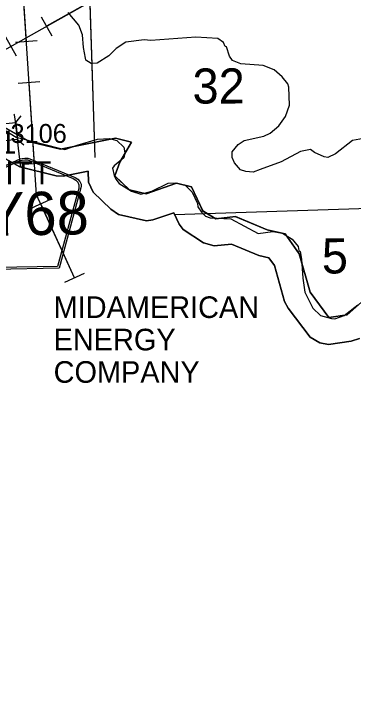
# Model space of a CAD drawing. Extents: x 128.7 to 185.5, y -21.4 to 12.6.
# Drawn here: x 153.067 to 154.322, y -14.949 to -12.371 of the extents above; entities that cross this region are included whole.
import ezdxf

# ---------------------------------------------------------------- set-up
doc = ezdxf.new("R2010")
doc.units = 0
for name, color, linetype in [('tdCoClipBndry', 7, 'Continuous'), ('tdCoCoBndry', 7, 'Continuous'), ('tdCoCoBndryPart', 7, 'Continuous'), ('tdCoHydroRiver', 7, 'Continuous'), ('tdCoPipe', 7, 'Continuous'), ('tdCoPipe1', 7, 'Continuous'), ('tdCoPipeTxt', 7, 'Continuous'), ('tdCoSecRdNmbr', 7, 'Continuous'), ('tdCoSecRteBand', 7, 'Continuous'), ('tdCoSectLine', 7, 'Continuous'), ('tdCoSectLinePart', 7, 'Continuous'), ('tdCoSectNmbr', 7, 'Continuous'), ('tdCoShieldCoRte', 7, 'Continuous'), ('tdCoStrucSec', 7, 'Continuous'), ('tdCoStrucSecCoName', 7, 'Continuous'), ('tdCoStrucSecFHWANum', 7, 'Continuous'), ('tdCoTwpBndryShd', 7, 'Continuous')]:
    doc.layers.add(name, color=color, linetype=linetype)

msp = doc.modelspace()

# ---------------------------------------------------------------- linework, layer by layer
at = {"layer": 'tdCoClipBndry'}
msp.add_lwpolyline([(154.346, -13.5734), (154.3158, -13.5834), (154.2319, -13.5954), (154.199, -13.5895), (154.1636, -13.5675), (154.0827, -13.4609), (154.069, -13.4354), (154.0313, -13.3028), (154.011, -13.2743), (153.974, -13.2653), (153.872, -13.2239), (153.8083, -13.2296), (153.7688, -13.219), (153.6938, -13.1699), (153.6788, -13.15), (153.6584, -13.1074), (153.5812, -13.1337), (153.5572, -13.1369), (153.4543, -13.1138), (153.4252, -13.0946), (153.3605, -13.0312), (153.3431, -12.9943), (153.3419, -12.9535), (153.2497, -12.9717), (153.2234, -12.9711), (153.0892, -12.9375), (153.0034, -12.8903)], dxfattribs=at)
at = {"layer": 'tdCoCoBndry'}
for p, q in [((153.1263, -12.8446), (152.9974, -12.772)), ((152.9974, -12.772), (153.1263, -12.8446)), ((153.4434, -12.8313), (153.239, -12.8723)), ((153.239, -12.8723), (153.4434, -12.8313)), ((153.5022, -12.8462), (153.4434, -12.8313)), ((153.4434, -12.8313), (153.5022, -12.8462)), ((153.239, -12.8723), (153.1263, -12.8446)), ((153.1263, -12.8446), (153.239, -12.8723)), ((153.4595, -12.92), (153.5022, -12.8462)), ((153.5022, -12.8462), (153.4595, -12.92)), ((153.4407, -12.971), (153.4595, -12.92)), ((153.4595, -12.92), (153.4407, -12.971)), ((153.4944, -13.0221), (153.4407, -12.971)), ((153.4407, -12.971), (153.4944, -13.0221)), ((153.6691, -12.998), (153.5567, -13.0369)), ((153.5567, -13.0369), (153.6691, -12.998)), ((153.7241, -13.0114), (153.6691, -12.998)), ((153.6691, -12.998), (153.7241, -13.0114)), ((153.7658, -13.1002), (153.7241, -13.0114)), ((153.7241, -13.0114), (153.7658, -13.1002)), ((153.5567, -13.0369), (153.4944, -13.0221)), ((153.4944, -13.0221), (153.5567, -13.0369)), ((153.8141, -13.1297), (153.7658, -13.1002)), ((153.7658, -13.1002), (153.8141, -13.1297)), ((153.8867, -13.1217), (153.8141, -13.1297)), ((153.8141, -13.1297), (153.8867, -13.1217)), ((154.0049, -13.1701), (153.8867, -13.1217)), ((153.8867, -13.1217), (154.0049, -13.1701)), ((154.0708, -13.1857), (154.0049, -13.1701)), ((154.0049, -13.1701), (154.0708, -13.1857)), ((154.1231, -13.2589), (154.0708, -13.1857)), ((154.0708, -13.1857), (154.1231, -13.2589)), ((154.1634, -13.4013), (154.1231, -13.2589)), ((154.1231, -13.2589), (154.1634, -13.4013)), ((154.2332, -13.4954), (154.1634, -13.4013)), ((154.1634, -13.4013), (154.2332, -13.4954)), ((154.3649, -13.4283), (154.3004, -13.4847)), ((154.3004, -13.4847), (154.3649, -13.4283)), ((154.3004, -13.4847), (154.2332, -13.4954)), ((154.2332, -13.4954), (154.3004, -13.4847))]:
    msp.add_line(p, q, dxfattribs=at)
for points in [[(152.997, -12.772), (153.126, -12.8446), (153.2387, -12.8723), (153.4431, -12.8313), (153.5018, -12.8462), (153.4591, -12.92), (153.4403, -12.971), (153.494, -13.0221), (153.5563, -13.0369), (153.6687, -12.998), (153.7238, -13.0114), (153.7654, -13.1002), (153.8138, -13.1297), (153.8863, -13.1217), (154.0045, -13.1701), (154.0704, -13.1857), (154.1227, -13.2589), (154.163, -13.4013), (154.2328, -13.4954), (154.3, -13.4847), (154.3645, -13.4283)], [(154.3649, -13.4283), (154.3004, -13.4847), (154.2332, -13.4954), (154.1634, -13.4013), (154.1231, -13.2589), (154.0708, -13.1857), (154.0049, -13.1701), (153.8867, -13.1217), (153.8141, -13.1297), (153.7658, -13.1002), (153.7241, -13.0114), (153.6691, -12.998), (153.5567, -13.0369), (153.4944, -13.0221), (153.4407, -12.971), (153.4595, -12.92), (153.5022, -12.8462), (153.4434, -12.8313), (153.239, -12.8723), (153.1263, -12.8446), (152.9974, -12.772)], [(154.3649, -13.4283), (154.3004, -13.4847), (154.2332, -13.4954), (154.1634, -13.4013), (154.1231, -13.2589), (154.0708, -13.1857), (154.0049, -13.1701), (153.8867, -13.1217), (153.8141, -13.1297), (153.7658, -13.1002), (153.7241, -13.0114), (153.6691, -12.998), (153.5567, -13.0369), (153.4944, -13.0221), (153.4407, -12.971), (153.4595, -12.92), (153.5022, -12.8462), (153.4434, -12.8313), (153.239, -12.8723), (153.1263, -12.8446), (152.9974, -12.772)], [(153.0034, -12.8903), (153.0892, -12.9375), (153.2234, -12.9711), (153.2497, -12.9717), (153.3419, -12.9535), (153.3431, -12.9943), (153.3605, -13.0312), (153.4252, -13.0946), (153.4543, -13.1138), (153.5572, -13.1369), (153.5812, -13.1337), (153.6584, -13.1074), (153.6788, -13.15), (153.6938, -13.1699), (153.7688, -13.219), (153.8083, -13.2296), (153.872, -13.2239), (153.974, -13.2653), (154.011, -13.2743), (154.0313, -13.3028), (154.069, -13.4354), (154.0827, -13.4609), (154.1636, -13.5675), (154.199, -13.5895), (154.2319, -13.5954), (154.3158, -13.5834), (154.346, -13.5734)]]:
    msp.add_lwpolyline(points, dxfattribs=at)
at = {"layer": 'tdCoCoBndryPart'}
msp.add_lwpolyline([(153.077, -12.817), (153.126, -12.8446), (153.2387, -12.8723), (153.4431, -12.8313), (153.5018, -12.8462), (153.4591, -12.92), (153.4403, -12.971), (153.494, -13.0221), (153.5563, -13.0369), (153.6687, -12.998), (153.7238, -13.0114), (153.7654, -13.1002), (153.8138, -13.1297), (153.8863, -13.1217), (154.0045, -13.1701), (154.0704, -13.1857), (154.1227, -13.2589), (154.163, -13.4013), (154.2328, -13.4954), (154.3, -13.4847), (154.3645, -13.4283)], dxfattribs=at)
at = {"layer": 'tdCoHydroRiver'}
for points in [[(154.3613, -12.8319), (154.3206, -12.8396), (154.2575, -12.8892), (154.2296, -12.9027), (154.2153, -12.9001), (154.18, -12.8839), (154.1654, -12.8734), (154.1278, -12.881), (154.0565, -12.9181), (153.9786, -12.9477), (153.9521, -12.9565), (153.9251, -12.9542), (153.906, -12.9486), (153.883, -12.9225), (153.8744, -12.9023), (153.8753, -12.8818), (153.8965, -12.8542), (153.9196, -12.8392), (153.9917, -12.8241), (154.015, -12.8122), (154.0472, -12.7859), (154.0728, -12.7503), (154.0872, -12.7087), (154.0849, -12.6425), (154.0813, -12.63), (154.0599, -12.6039), (154.0306, -12.5781), (153.989, -12.5622), (153.9067, -12.5555), (153.8763, -12.5439), (153.8647, -12.527), (153.8541, -12.4926), (153.8493, -12.4912), (153.8425, -12.4772), (153.8215, -12.4622), (153.7408, -12.457), (153.5739, -12.4691), (153.5485, -12.4668), (153.481, -12.4754), (153.4455, -12.4987), (153.418, -12.5265), (153.3747, -12.5533), (153.3527, -12.554), (153.3333, -12.5421), (153.3315, -12.5342), (153.3238, -12.495), (153.3206, -12.4478), (153.3067, -12.412), (153.2673, -12.366)], [(153.0071, -12.7869), (153.0748, -12.8271), (153.2547, -12.8731), (153.3015, -12.8573), (153.3765, -12.8342), (153.4206, -12.8326), (153.4477, -12.8396), (153.4738, -12.864), (153.4777, -12.8859), (153.4736, -12.9034), (153.4383, -12.9331), (153.4323, -12.9427), (153.4379, -12.9694), (153.4447, -12.9833), (153.4563, -12.9987), (153.5015, -13.0272), (153.5366, -13.0386), (153.5773, -13.0277), (153.6378, -12.9972), (153.6662, -12.9963), (153.7012, -13.0045), (153.7273, -13.0305), (153.7461, -13.0724), (153.7481, -13.085), (153.7614, -13.1051), (153.7762, -13.1203), (153.7937, -13.126), (153.8696, -13.1298), (153.9709, -13.1847), (154.0259, -13.1765), (154.0609, -13.1832), (154.0964, -13.2056), (154.1193, -13.2317), (154.1215, -13.2474), (154.1263, -13.2504), (154.132, -13.2786), (154.136, -13.3495), (154.1441, -13.4013), (154.173, -13.4603), (154.2023, -13.4877), (154.2422, -13.4989), (154.2548, -13.5001), (154.2891, -13.4879), (154.3399, -13.4482)]]:
    msp.add_lwpolyline(points, dxfattribs=at)
at = {"layer": 'tdCoPipe'}
for p, q in [((153.1532, -12.4711), (153.0729, -12.4764)), ((153.1633, -12.6229), (153.0828, -12.6282)), ((153.1831, -12.9234), (153.1028, -12.9287)), ((153.2027, -13.0579), (153.1293, -13.0913)), ((153.3274, -13.332), (153.2542, -13.3654))]:
    msp.add_line(p, q, dxfattribs=at)
for points in [[(153.2907, -13.3487), (153.1504, -13.0403), (153.08, -11.9742), (153.9221, -10.7441), (153.8422, -9.1961), (152.4885, -6.1792), (152.255, -4.5804), (152.0586, -4.5041), (150.9187, -1.6917), (149.9982, 2.3236), (149.759, 2.5022), (149.1601, 4.9961)], [(141.862, -14.949), (144.0814, -14.2683), (145.7745, -13.7388), (145.9312, -13.6747), (145.9234, -13.4239), (152.8711, -12.5946), (153.879, -12.0272), (155.1085, -11.9148), (156.3627, -11.7638), (158.9313, -11.5045), (162.8631, -11.1506)], [(153.113, -12.4738), (153.0932, -12.1732)], [(153.1429, -12.9261), (153.123, -12.6256)], [(153.2907, -13.3487), (153.166, -13.0746)]]:
    msp.add_lwpolyline(points, dxfattribs=at)
at = {"layer": 'tdCoPipe1'}
for p, q in [((153.1679, -12.3813), (153.2074, -12.4515)), ((153.0353, -12.4559), (153.0748, -12.526))]:
    msp.add_line(p, q, dxfattribs=at)
msp.add_lwpolyline([(153.4501, -12.2686), (153.1877, -12.4164)], dxfattribs=at)
at = {"layer": 'tdCoSecRteBand'}
msp.add_lwpolyline([(153.0667, -12.7418), (153.0671, -12.7434), (153.0674, -12.745), (153.0701, -12.7605), (153.0702, -12.7609), (153.0702, -12.7612), (153.0715, -12.7695), (153.0716, -12.7704), (153.0717, -12.7709), (153.0718, -12.7715), (153.0775, -12.8227), (153.0829, -12.8684), (153.083, -12.8685), (153.083, -12.8686), (153.0876, -12.9097), (153.0911, -12.938)], dxfattribs=at)
at = {"layer": 'tdCoSectLine'}
for points in [[(153.341, -12.1094), (153.3662, -12.9023)], [(153.6612, -13.1133), (154.3818, -13.0902)]]:
    msp.add_lwpolyline(points, dxfattribs=at)
at = {"layer": 'tdCoSectLinePart'}
for points in [[(153.342, -12.1394), (153.3662, -12.9023)], [(153.6612, -13.1133), (154.3818, -13.0902)]]:
    msp.add_lwpolyline(points, dxfattribs=at)
at = {"layer": 'tdCoShieldCoRte'}
for points in [[(152.9949, -13.317), (152.908, -13.0356), (152.9039, -13.0225), (152.9031, -13.0166), (152.9029, -13.0088), (152.907, -12.9984), (152.9141, -12.9898), (152.9236, -12.983), (153.0896, -12.9077), (153.097, -12.9059), (153.1074, -12.9048), (153.1179, -12.9056), (153.1254, -12.9071), (153.2939, -12.9765), (153.3036, -12.983), (153.3111, -12.9914), (153.3155, -13.0016), (153.3156, -13.0094), (153.315, -13.0153), (153.3113, -13.0285), (153.2343, -13.3128)], [(153.0006, -13.3106), (152.9161, -13.0367), (152.9121, -13.0242), (152.9113, -13.0185), (152.9112, -13.011), (152.9151, -13.001), (152.922, -12.9928), (152.931, -12.9862), (153.0904, -12.914), (153.0976, -12.9123), (153.1076, -12.9112), (153.1176, -12.9119), (153.1248, -12.9134), (153.2866, -12.98), (153.2959, -12.9862), (153.303, -12.9943), (153.3073, -13.0041), (153.3074, -13.0116), (153.3068, -13.0173), (153.3033, -13.03), (153.2284, -13.3066)]]:
    msp.add_lwpolyline(points, close=True, dxfattribs=at)
at = {"layer": 'tdCoStrucSec'}
for p, q in [((153.0736, -12.7732), (153.0934, -12.7489)), ((153.0799, -12.8355), (153.1041, -12.8552))]:
    msp.add_line(p, q, dxfattribs=at)
msp.add_lwpolyline([(153.0176, -12.8417), (153.0113, -12.7795), (153.0736, -12.7732), (153.0799, -12.8355)], close=True, dxfattribs=at)
at = {"layer": 'tdCoTwpBndryShd'}
msp.add_lwpolyline([(152.997, -12.772), (153.126, -12.8446), (153.2387, -12.8723), (153.4431, -12.8313), (153.5018, -12.8462), (153.4591, -12.92), (153.4403, -12.971), (153.494, -13.0221), (153.5563, -13.0369), (153.6687, -12.998), (153.7238, -13.0114), (153.7654, -13.1002), (153.8138, -13.1297), (153.8863, -13.1217), (154.0045, -13.1701), (154.0704, -13.1857), (154.1227, -13.2589), (154.163, -13.4013), (154.2328, -13.4954), (154.3, -13.4847), (154.3645, -13.4283)], dxfattribs=at)

# ---------------------------------------------------------------- texts
at = {"layer": 'tdCoPipeTxt'}
for s, p in [('MIDAMERICAN', (153.2138, -13.4969)), ('ENERGY', (153.2138, -13.6169)), ('COMPANY', (153.2138, -13.7369))]:
    msp.add_text(s, height=0.08, rotation=359.9957, dxfattribs=at).set_placement(p)
at = {"layer": 'tdCoSecRdNmbr'}
msp.add_text('3106', height=0.07, rotation=0.1154, dxfattribs=at).set_placement((153.0543, -12.8489))
at = {"layer": 'tdCoSectNmbr'}
for s, rotation, p in [('32', 0.1164, (153.7281, -12.703)), ('5', 0.1179, (154.2069, -13.3322))]:
    msp.add_text(s, height=0.13, rotation=rotation, dxfattribs=at).set_placement(p)
at = {"layer": 'tdCoShieldCoRte'}
msp.add_text('Y68', height=0.16, rotation=1, dxfattribs=at).set_placement((152.9645, -13.1932))
at = {"layer": 'tdCoStrucSecCoName'}
msp.add_text('31 DEWITT', height=0.085, dxfattribs=at).set_placement((152.6116, -13.0015))
at = {"layer": 'tdCoStrucSecFHWANum'}
msp.add_text('20871', height=0.085, dxfattribs=at).set_placement((152.76, -12.8886))

doc.saveas('drawing.dxf')
